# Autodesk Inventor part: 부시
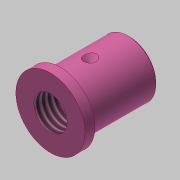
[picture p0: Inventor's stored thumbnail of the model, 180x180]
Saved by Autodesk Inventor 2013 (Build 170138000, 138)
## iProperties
Created: 2019-04
Part Number: 부시
Material: 강철, 연강
Document SubType Name: Modeling
Designer: mduedu
Density: 1 g/cm^3
Author: mduedu
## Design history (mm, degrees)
sketch "스케치1"
  geometry: L1 (0, 0)-(3, 0); L2 (3, 0)-(3, 10.5); L3 (3, 10.5)-(0, 10.5); L4 (0, 10.5)-(0, 0); L5 (3, 0)-(24, 0); L6 (24, 0)-(24, 8.5); L7 (24, 8.5)-(3, 8.5); L8 (3, 8.5)-(3, 0)
  constraints: 16 end point, 4 parallel, 2 horizontal, 2 perpendicular
  dimensions: "d0" = 3 distance of L2.end L3.end; "d2" = 24 distance between parallel lines of L6 L4; "d3" = 17 diameter of L7 L5; "d4" = 21 diameter of L3 L1
revolve "회전1" sketch "스케치1" stored, may be unused: angle "d5" = 90 deg
sketch "스케치2"
  geometry: L1 (3, 8.5)-(24, 8.5) reference; L2 (12, 8.5)-(12, 6.5); L3 (12, 6.5)-(14, 8.5); L4 (0, -10.5)-(0, 10.5) reference; 1 further point
  constraints: 4 end point, 2 point on line, 1 perpendicular
  dimensions: "d6" = 12 distance from line of L2.start L4; "d7" = 2 distance of L2.start L3.end; "d8" = 45 deg angle of L3 L2
revolve "회전2" sketch "스케치2" stored, may be unused: angle "d9" = 90 deg
hole "구멍1" diameter "d12" = 10.106; stored, may be unused: countersink angle "d16" = 90 deg, drill point angle "d18" = 118 deg; dims "d10" = 10, "d11" = 10, "d13" = 39, "d14" = 4, "d15" = 2, "d17" = 8
chamfer "모따기1" distance "d19" = 0.5; stored, may be unused: second distance "d20" = 2, angle "d21" = 45 deg
node "작업점1"
  node "작업 평면1"
  node "작업축1"
node "솔리드1"
